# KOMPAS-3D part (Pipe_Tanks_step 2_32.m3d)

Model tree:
1. X Axis
2. Y Axis
3. Z Axis  (labels: T-Bend Dn 50; Pipe Dn 50)
     Òîëùèíà ñòåíêè 1 = 1

Referenced files in C:\Documents and Settings\kashirsky\Мои документы\Camtasia Studio\Pipelines3D\Tanks\: Tanks_step 2.a3d
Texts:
  Pipe Dn 50
  Steel ASTM A295
  Three Point Plane
  Plane at Angle
  Line and Point Plane
  Axis through Two Vertices
  Axis of Feature
  Axis of Conical Surface
  Axis through Edge
  Trim by Surface
  Trim by Sketch
  Feature with No History
  Intersection Axis of Two Planes
  Two Line Plane
  Line and Face Plane
  Bend by line
  Hole in sheet body
  Cut in sheet body
  Point in CM
  Linear Dimension from Line to Point
  Surface Finish Symbol
  Geometric Tolerance Symbol
  Leader #1
  Leader #2
  Leader #3
  Shape Deviations and Datum
  Node point number
  Mark of coordination axis
  Node point designation
  Mark/Reference designation with leader
  Mark/reference designation on line
  Mark/Reference designation without leader
  T-Bend Dn 50
  Plane of section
